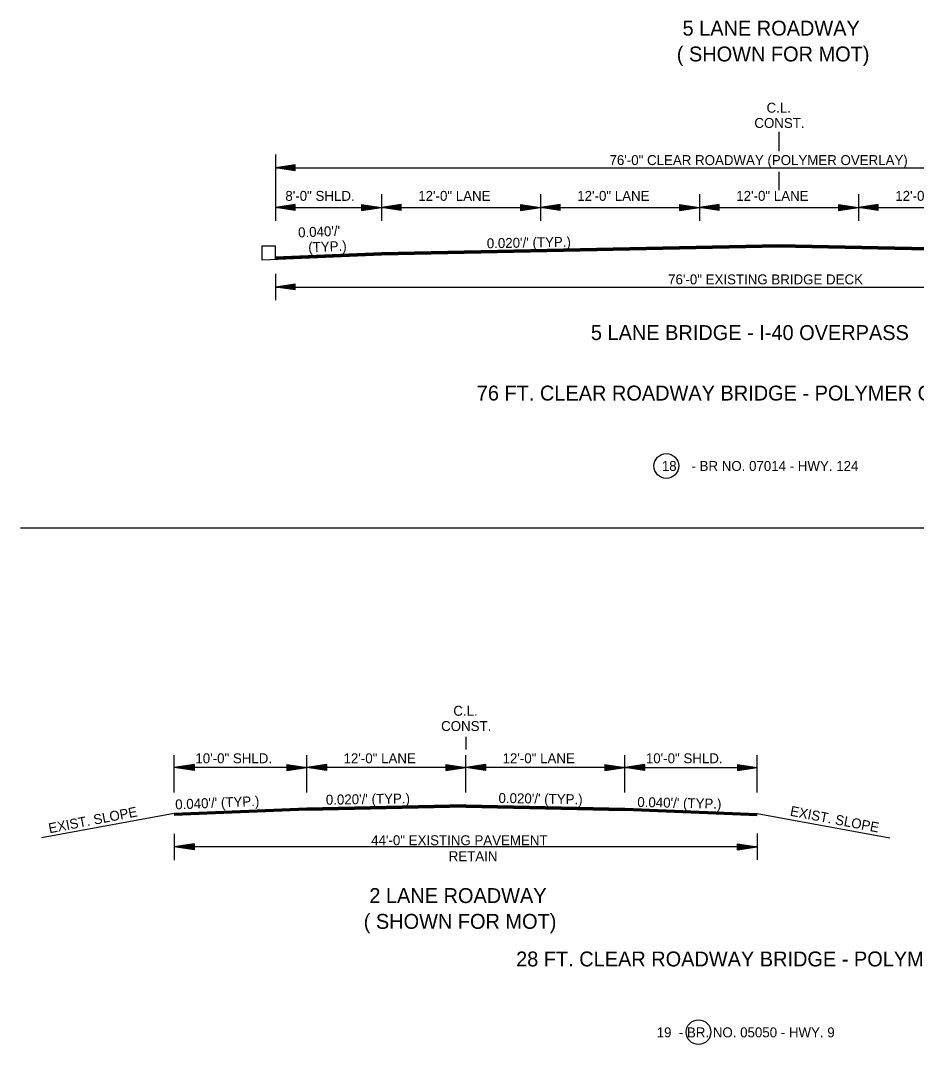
# Model space of a CAD drawing. Extents: x 550980 to 1930787, y -1972975 to 596640.
# Drawn here: x 551009 to 551685, y -1954146 to -1953373 of the extents above; entities that cross this region are included whole.
import ezdxf

# ---------------------------------------------------------------- set-up
doc = ezdxf.new("R2010")
doc.units = 0
doc.layers.add('R_Border', color=7, linetype='Continuous')
doc.layers.add('R_Draft', color=7, linetype='Continuous')

msp = doc.modelspace()

# ---------------------------------------------------------------- linework, layer by layer
at = {"layer": 'R_Border'}
for p, q in [((551581.34, -1953457.37), (551581.34, -1953471.87)), ((551201.34, -1953474.37), (551201.34, -1953524.37)), ((551216.34, -1953482.12), (551201.34, -1953484.37)), ((551201.34, -1953484.37), (551961.34, -1953484.37)), ((551216.34, -1953486.62), (551201.34, -1953484.37)), ((551216.34, -1953482.5), (551203.84, -1953484.37)), ((551216.34, -1953486.25), (551203.84, -1953484.37)), ((551216.34, -1953482.88), (551206.42, -1953484.37)), ((551216.34, -1953485.86), (551206.42, -1953484.37)), ((551216.34, -1953483.25), (551208.92, -1953484.37)), ((551216.34, -1953485.49), (551208.92, -1953484.37)), ((551216.34, -1953483.64), (551211.46, -1953484.37)), ((551216.34, -1953485.1), (551211.46, -1953484.37)), ((551216.34, -1953484.02), (551213.97, -1953484.37)), ((551216.34, -1953484.72), (551213.97, -1953484.37)), ((551216.34, -1953486.62), (551216.34, -1953482.12)), ((551581.34, -1953487.37), (551581.34, -1953501.37)), ((551281.34, -1953504.37), (551281.34, -1953524.37)), ((551401.34, -1953504.37), (551401.34, -1953524.37)), ((551521.34, -1953504.37), (551521.34, -1953524.37)), ((551641.34, -1953504.37), (551641.34, -1953524.37)), ((551216.34, -1953512.12), (551201.34, -1953514.37)), ((551201.34, -1953514.37), (551961.34, -1953514.37)), ((551216.34, -1953516.62), (551201.34, -1953514.37)), ((551216.34, -1953512.5), (551203.84, -1953514.37)), ((551216.34, -1953516.25), (551203.84, -1953514.37)), ((551216.34, -1953512.88), (551206.42, -1953514.37)), ((551216.34, -1953515.86), (551206.42, -1953514.37)), ((551216.34, -1953513.25), (551208.92, -1953514.37)), ((551216.34, -1953515.49), (551208.92, -1953514.37)), ((551216.34, -1953513.64), (551211.46, -1953514.37)), ((551216.34, -1953515.1), (551211.46, -1953514.37)), ((551216.34, -1953514.02), (551213.97, -1953514.37)), ((551216.34, -1953514.72), (551213.97, -1953514.37)), ((551216.34, -1953516.62), (551216.34, -1953512.12)), ((551266.34, -1953512.12), (551281.34, -1953514.37)), ((551266.34, -1953512.12), (551266.34, -1953516.62)), ((551266.34, -1953512.5), (551278.83, -1953514.37)), ((551266.34, -1953512.88), (551276.25, -1953514.37)), ((551266.34, -1953513.25), (551273.76, -1953514.37)), ((551266.34, -1953513.64), (551271.21, -1953514.37)), ((551266.34, -1953514.02), (551268.71, -1953514.37)), ((551266.34, -1953516.62), (551281.34, -1953514.37)), ((551266.34, -1953515.11), (551271.21, -1953514.37)), ((551266.34, -1953515.86), (551276.25, -1953514.37)), ((551266.34, -1953516.25), (551278.83, -1953514.37)), ((551266.34, -1953515.49), (551273.76, -1953514.37)), ((551266.34, -1953514.72), (551268.71, -1953514.37)), ((551296.34, -1953512.12), (551281.34, -1953514.37)), ((551296.34, -1953516.62), (551281.34, -1953514.37)), ((551296.34, -1953512.5), (551283.84, -1953514.37)), ((551296.34, -1953516.25), (551283.84, -1953514.37)), ((551296.34, -1953512.88), (551286.42, -1953514.37)), ((551296.34, -1953515.86), (551286.42, -1953514.37)), ((551296.34, -1953513.25), (551288.92, -1953514.37)), ((551296.34, -1953515.49), (551288.92, -1953514.37)), ((551296.34, -1953513.64), (551291.46, -1953514.37)), ((551296.34, -1953515.1), (551291.46, -1953514.37)), ((551296.34, -1953514.02), (551293.97, -1953514.37)), ((551296.34, -1953514.72), (551293.97, -1953514.37)), ((551296.34, -1953516.62), (551296.34, -1953512.12)), ((551386.34, -1953512.12), (551401.34, -1953514.37)), ((551386.34, -1953512.12), (551386.34, -1953516.62)), ((551386.34, -1953512.5), (551398.83, -1953514.37)), ((551386.34, -1953512.88), (551396.25, -1953514.37)), ((551386.34, -1953513.25), (551393.76, -1953514.37)), ((551386.34, -1953513.64), (551391.21, -1953514.37)), ((551386.34, -1953514.02), (551388.71, -1953514.37)), ((551386.34, -1953516.62), (551401.34, -1953514.37)), ((551386.34, -1953515.11), (551391.21, -1953514.37)), ((551386.34, -1953515.86), (551396.25, -1953514.37)), ((551386.34, -1953516.25), (551398.83, -1953514.37)), ((551386.34, -1953515.49), (551393.76, -1953514.37)), ((551386.34, -1953514.72), (551388.71, -1953514.37)), ((551416.34, -1953512.12), (551401.34, -1953514.37)), ((551416.34, -1953516.62), (551401.34, -1953514.37)), ((551416.34, -1953512.5), (551403.84, -1953514.37)), ((551416.34, -1953516.25), (551403.84, -1953514.37)), ((551416.34, -1953512.88), (551406.42, -1953514.37)), ((551416.34, -1953515.86), (551406.42, -1953514.37)), ((551416.34, -1953513.25), (551408.92, -1953514.37)), ((551416.34, -1953515.49), (551408.92, -1953514.37)), ((551416.34, -1953513.64), (551411.46, -1953514.37)), ((551416.34, -1953515.1), (551411.46, -1953514.37)), ((551416.34, -1953514.02), (551413.97, -1953514.37)), ((551416.34, -1953514.72), (551413.97, -1953514.37)), ((551416.34, -1953516.62), (551416.34, -1953512.12)), ((551506.34, -1953512.12), (551521.34, -1953514.37)), ((551506.34, -1953512.12), (551506.34, -1953516.62)), ((551506.34, -1953512.5), (551518.83, -1953514.37)), ((551506.34, -1953512.88), (551516.25, -1953514.37)), ((551506.34, -1953513.25), (551513.76, -1953514.37)), ((551506.34, -1953513.64), (551511.21, -1953514.37)), ((551506.34, -1953514.02), (551508.71, -1953514.37)), ((551506.34, -1953516.62), (551521.34, -1953514.37)), ((551506.34, -1953515.11), (551511.21, -1953514.37)), ((551506.34, -1953515.86), (551516.25, -1953514.37)), ((551506.34, -1953516.25), (551518.83, -1953514.37)), ((551506.34, -1953515.49), (551513.76, -1953514.37)), ((551506.34, -1953514.72), (551508.71, -1953514.37)), ((551536.34, -1953512.12), (551521.34, -1953514.37)), ((551536.34, -1953516.62), (551521.34, -1953514.37)), ((551536.34, -1953512.5), (551523.84, -1953514.37)), ((551536.34, -1953516.25), (551523.84, -1953514.37)), ((551536.34, -1953512.88), (551526.42, -1953514.37)), ((551536.34, -1953515.86), (551526.42, -1953514.37)), ((551536.34, -1953513.25), (551528.92, -1953514.37)), ((551536.34, -1953515.49), (551528.92, -1953514.37)), ((551536.34, -1953513.64), (551531.46, -1953514.37)), ((551536.34, -1953515.1), (551531.46, -1953514.37)), ((551536.34, -1953514.02), (551533.97, -1953514.37)), ((551536.34, -1953514.72), (551533.97, -1953514.37)), ((551536.34, -1953516.62), (551536.34, -1953512.12)), ((551626.34, -1953512.12), (551641.34, -1953514.37)), ((551626.34, -1953512.12), (551626.34, -1953516.62)), ((551626.34, -1953512.5), (551638.83, -1953514.37)), ((551626.34, -1953512.88), (551636.25, -1953514.37)), ((551626.34, -1953513.25), (551633.76, -1953514.37)), ((551626.34, -1953513.64), (551631.21, -1953514.37)), ((551626.34, -1953514.02), (551628.71, -1953514.37)), ((551626.34, -1953516.62), (551641.34, -1953514.37)), ((551626.34, -1953515.11), (551631.21, -1953514.37)), ((551626.34, -1953515.86), (551636.25, -1953514.37)), ((551626.34, -1953516.25), (551638.83, -1953514.37)), ((551626.34, -1953515.49), (551633.76, -1953514.37)), ((551626.34, -1953514.72), (551628.71, -1953514.37)), ((551656.34, -1953512.12), (551641.34, -1953514.37)), ((551656.34, -1953516.62), (551641.34, -1953514.37)), ((551656.34, -1953512.5), (551643.84, -1953514.37)), ((551656.34, -1953516.25), (551643.84, -1953514.37)), ((551656.34, -1953512.88), (551646.42, -1953514.37)), ((551656.34, -1953515.86), (551646.42, -1953514.37)), ((551656.34, -1953513.25), (551648.92, -1953514.37)), ((551656.34, -1953515.49), (551648.92, -1953514.37)), ((551656.34, -1953513.64), (551651.46, -1953514.37)), ((551656.34, -1953515.1), (551651.46, -1953514.37)), ((551656.34, -1953514.02), (551653.97, -1953514.37)), ((551656.34, -1953514.72), (551653.97, -1953514.37)), ((551656.34, -1953516.62), (551656.34, -1953512.12)), ((551201.34, -1953543.66), (551191.17, -1953543.66)), ((551191.17, -1953543.66), (551191.17, -1953553.78)), ((551201.34, -1953553.07), (551201.34, -1953543.66)), ((551201.34, -1953564.37), (551201.34, -1953584.37)), ((551216.34, -1953572.12), (551201.34, -1953574.37)), ((551201.34, -1953574.37), (551961.34, -1953574.37)), ((551216.34, -1953576.62), (551201.34, -1953574.37)), ((551216.34, -1953572.5), (551203.84, -1953574.37)), ((551216.34, -1953576.25), (551203.84, -1953574.37)), ((551216.34, -1953572.88), (551206.42, -1953574.37)), ((551216.34, -1953575.86), (551206.42, -1953574.37)), ((551216.34, -1953573.25), (551208.92, -1953574.37)), ((551216.34, -1953575.49), (551208.92, -1953574.37)), ((551216.34, -1953573.64), (551211.46, -1953574.37)), ((551216.34, -1953575.1), (551211.46, -1953574.37)), ((551216.34, -1953574.02), (551213.97, -1953574.37)), ((551216.34, -1953574.72), (551213.97, -1953574.37)), ((551216.34, -1953576.62), (551216.34, -1953572.12)), ((551008.97, -1953755.99), (552070.24, -1953755.99)), ((551344.96, -1953913.64), (551344.96, -1953923.19))]:
    msp.add_line(p, q, dxfattribs=at)
for points in [[(551191.17, -1953553.78), (551281.34, -1953550.17), (551581.34, -1953544.17), (551881.34, -1953550.17), (551971.51, -1953553.78)], [(551201.34, -1953551.57), (551281.34, -1953548.37), (551581.34, -1953542.37), (551881.34, -1953548.37), (551961.34, -1953551.57)], [(551201.34, -1953551.87), (551281.34, -1953548.67), (551581.34, -1953542.67), (551881.34, -1953548.67), (551961.34, -1953551.87)], [(551201.34, -1953552.17), (551281.34, -1953548.97), (551581.34, -1953542.97), (551881.34, -1953548.97), (551961.34, -1953552.17)], [(551201.34, -1953552.47), (551281.34, -1953549.27), (551581.34, -1953543.27), (551881.34, -1953549.27), (551961.34, -1953552.47)], [(551201.34, -1953552.77), (551281.34, -1953549.57), (551581.34, -1953543.57), (551881.34, -1953549.57), (551961.34, -1953552.77)], [(551201.34, -1953553.07), (551281.34, -1953549.87), (551581.34, -1953543.87), (551881.34, -1953549.87), (551961.34, -1953553.07)]]:
    msp.add_lwpolyline(points, dxfattribs=at)
for centre in [(551496.34, -1953709.37), (551520.64, -1954136.51)]:
    msp.add_circle(centre, 9.34, dxfattribs=at)
at = {"layer": 'R_Draft'}
for p, q in [((551124.96, -1953955.6), (551124.96, -1953927.64)), ((551139.96, -1953934.58), (551124.96, -1953936.83)), ((551139.96, -1953934.58), (551139.96, -1953939.08)), ((551209.96, -1953934.58), (551224.96, -1953936.83)), ((551209.96, -1953934.58), (551209.96, -1953939.08)), ((551224.96, -1953955.6), (551224.96, -1953927.64)), ((551239.96, -1953934.58), (551224.96, -1953936.83)), ((551239.96, -1953934.58), (551239.96, -1953939.08)), ((551329.96, -1953934.58), (551344.96, -1953936.83)), ((551329.96, -1953934.58), (551329.96, -1953939.08)), ((551344.96, -1953955.6), (551344.96, -1953927.64)), ((551359.96, -1953934.58), (551344.96, -1953936.83)), ((551359.96, -1953934.58), (551359.96, -1953939.08)), ((551449.96, -1953934.58), (551464.96, -1953936.83)), ((551449.96, -1953934.58), (551449.96, -1953939.08)), ((551464.96, -1953955.6), (551464.96, -1953927.64)), ((551479.96, -1953934.58), (551464.96, -1953936.83)), ((551479.96, -1953934.58), (551479.96, -1953939.08)), ((551549.96, -1953934.58), (551564.96, -1953936.83)), ((551549.96, -1953934.58), (551549.96, -1953939.08)), ((551564.96, -1953955.6), (551564.96, -1953927.64)), ((551224.96, -1953936.83), (551124.96, -1953936.83)), ((551139.96, -1953939.08), (551124.96, -1953936.83)), ((551139.96, -1953934.96), (551127.47, -1953936.83)), ((551139.96, -1953938.71), (551127.47, -1953936.83)), ((551139.96, -1953935.34), (551130.05, -1953936.83)), ((551139.96, -1953938.33), (551130.05, -1953936.83)), ((551139.96, -1953935.72), (551132.55, -1953936.83)), ((551139.96, -1953937.95), (551132.55, -1953936.83)), ((551139.96, -1953936.11), (551135.09, -1953936.83)), ((551139.96, -1953937.57), (551135.09, -1953936.83)), ((551139.96, -1953936.48), (551137.59, -1953936.83)), ((551139.96, -1953937.19), (551137.59, -1953936.83)), ((551209.96, -1953934.96), (551222.46, -1953936.83)), ((551209.96, -1953935.34), (551219.88, -1953936.83)), ((551209.96, -1953935.72), (551217.38, -1953936.83)), ((551209.96, -1953936.11), (551214.84, -1953936.83)), ((551209.96, -1953936.48), (551212.33, -1953936.83)), ((551209.96, -1953939.08), (551224.96, -1953936.83)), ((551209.96, -1953937.57), (551214.84, -1953936.83)), ((551209.96, -1953938.33), (551219.88, -1953936.83)), ((551209.96, -1953938.71), (551222.46, -1953936.83)), ((551209.96, -1953937.95), (551217.38, -1953936.83)), ((551209.96, -1953937.19), (551212.33, -1953936.83)), ((551344.96, -1953936.83), (551224.96, -1953936.83)), ((551239.96, -1953939.08), (551224.96, -1953936.83)), ((551239.96, -1953934.96), (551227.47, -1953936.83)), ((551239.96, -1953938.71), (551227.47, -1953936.83)), ((551239.96, -1953935.34), (551230.05, -1953936.83)), ((551239.96, -1953938.33), (551230.05, -1953936.83)), ((551239.96, -1953935.72), (551232.55, -1953936.83)), ((551239.96, -1953937.95), (551232.55, -1953936.83)), ((551239.96, -1953936.11), (551235.09, -1953936.83)), ((551239.96, -1953937.57), (551235.09, -1953936.83)), ((551239.96, -1953936.48), (551237.59, -1953936.83)), ((551239.96, -1953937.19), (551237.59, -1953936.83)), ((551329.96, -1953934.96), (551342.46, -1953936.83)), ((551329.96, -1953935.34), (551339.88, -1953936.83)), ((551329.96, -1953935.72), (551337.38, -1953936.83)), ((551329.96, -1953936.11), (551334.84, -1953936.83)), ((551329.96, -1953936.48), (551332.33, -1953936.83)), ((551329.96, -1953939.08), (551344.96, -1953936.83)), ((551329.96, -1953937.57), (551334.84, -1953936.83)), ((551329.96, -1953938.33), (551339.88, -1953936.83)), ((551329.96, -1953938.71), (551342.46, -1953936.83)), ((551329.96, -1953937.95), (551337.38, -1953936.83)), ((551329.96, -1953937.19), (551332.33, -1953936.83)), ((551464.96, -1953936.83), (551344.96, -1953936.83)), ((551359.96, -1953939.08), (551344.96, -1953936.83)), ((551359.96, -1953934.96), (551347.47, -1953936.83)), ((551359.96, -1953938.71), (551347.47, -1953936.83)), ((551359.96, -1953935.34), (551350.05, -1953936.83)), ((551359.96, -1953938.33), (551350.05, -1953936.83)), ((551359.96, -1953935.72), (551352.55, -1953936.83)), ((551359.96, -1953937.95), (551352.55, -1953936.83)), ((551359.96, -1953936.11), (551355.09, -1953936.83)), ((551359.96, -1953937.57), (551355.09, -1953936.83)), ((551359.96, -1953936.48), (551357.59, -1953936.83)), ((551359.96, -1953937.19), (551357.59, -1953936.83)), ((551449.96, -1953934.96), (551462.46, -1953936.83)), ((551449.96, -1953935.34), (551459.88, -1953936.83)), ((551449.96, -1953935.72), (551457.38, -1953936.83)), ((551449.96, -1953936.11), (551454.84, -1953936.83)), ((551449.96, -1953936.48), (551452.33, -1953936.83)), ((551449.96, -1953939.08), (551464.96, -1953936.83)), ((551449.96, -1953937.57), (551454.84, -1953936.83)), ((551449.96, -1953938.33), (551459.88, -1953936.83)), ((551449.96, -1953938.71), (551462.46, -1953936.83)), ((551449.96, -1953937.95), (551457.38, -1953936.83)), ((551449.96, -1953937.19), (551452.33, -1953936.83)), ((551464.96, -1953936.83), (551564.96, -1953936.83)), ((551479.96, -1953939.08), (551464.96, -1953936.83)), ((551479.96, -1953934.96), (551467.47, -1953936.83)), ((551479.96, -1953938.71), (551467.47, -1953936.83)), ((551479.96, -1953935.34), (551470.05, -1953936.83)), ((551479.96, -1953938.33), (551470.05, -1953936.83)), ((551479.96, -1953935.72), (551472.55, -1953936.83)), ((551479.96, -1953937.95), (551472.55, -1953936.83)), ((551479.96, -1953936.11), (551475.09, -1953936.83)), ((551479.96, -1953937.57), (551475.09, -1953936.83)), ((551479.96, -1953936.48), (551477.59, -1953936.83)), ((551479.96, -1953937.19), (551477.59, -1953936.83)), ((551549.96, -1953934.96), (551562.46, -1953936.83)), ((551549.96, -1953935.34), (551559.88, -1953936.83)), ((551549.96, -1953935.72), (551557.38, -1953936.83)), ((551549.96, -1953936.11), (551554.84, -1953936.83)), ((551549.96, -1953936.48), (551552.33, -1953936.83)), ((551549.96, -1953939.08), (551564.96, -1953936.83)), ((551549.96, -1953937.57), (551554.84, -1953936.83)), ((551549.96, -1953938.33), (551559.88, -1953936.83)), ((551549.96, -1953938.71), (551562.46, -1953936.83)), ((551549.96, -1953937.95), (551557.38, -1953936.83)), ((551549.96, -1953937.19), (551552.33, -1953936.83)), ((551344.96, -1953965.14), (551224.96, -1953967.54)), ((551344.96, -1953965.44), (551224.96, -1953967.84)), ((551344.96, -1953965.74), (551224.96, -1953968.14)), ((551344.96, -1953965.14), (551464.96, -1953967.54)), ((551344.96, -1953965.44), (551464.96, -1953967.84)), ((551344.96, -1953965.74), (551464.96, -1953968.14)), ((551124.96, -1953971.54), (551024.9, -1953989.92)), ((551224.96, -1953967.54), (551124.96, -1953971.54)), ((551224.96, -1953967.84), (551124.96, -1953971.84)), ((551224.96, -1953968.14), (551124.96, -1953972.14)), ((551224.96, -1953968.44), (551124.96, -1953972.44)), ((551224.96, -1953968.74), (551124.96, -1953972.74)), ((551224.96, -1953969.04), (551124.96, -1953973.04)), ((551344.96, -1953966.04), (551224.96, -1953968.44)), ((551344.96, -1953966.34), (551224.96, -1953968.74)), ((551344.96, -1953966.64), (551224.96, -1953969.04)), ((551344.96, -1953966.81), (551224.96, -1953969.21)), ((551344.96, -1953966.04), (551464.96, -1953968.44)), ((551344.96, -1953966.34), (551464.96, -1953968.74)), ((551344.96, -1953966.64), (551464.96, -1953969.04)), ((551344.96, -1953966.81), (551464.96, -1953969.21)), ((551464.96, -1953967.54), (551564.96, -1953971.54)), ((551464.96, -1953967.84), (551564.96, -1953971.84)), ((551464.96, -1953968.14), (551564.96, -1953972.14)), ((551464.96, -1953968.44), (551564.96, -1953972.44)), ((551464.96, -1953968.74), (551564.96, -1953972.74)), ((551464.96, -1953969.04), (551564.96, -1953973.04)), ((551564.96, -1953971.54), (551665.03, -1953989.92)), ((551124.96, -1953986.8), (551124.96, -1954006.8)), ((551564.96, -1953986.55), (551564.96, -1954006.55)), ((551139.96, -1953994.55), (551124.96, -1953996.8)), ((551139.96, -1953994.93), (551127.47, -1953996.8)), ((551139.96, -1953995.31), (551130.05, -1953996.8)), ((551139.96, -1953995.68), (551132.55, -1953996.8)), ((551139.96, -1953996.07), (551135.09, -1953996.8)), ((551139.96, -1953996.45), (551137.59, -1953996.8)), ((551139.96, -1953994.55), (551139.96, -1953999.05)), ((551549.96, -1953994.55), (551564.96, -1953996.8)), ((551549.96, -1953999.05), (551549.96, -1953994.55)), ((551549.96, -1953994.93), (551562.46, -1953996.8)), ((551549.96, -1953995.31), (551559.88, -1953996.8)), ((551549.96, -1953995.68), (551557.38, -1953996.8)), ((551549.96, -1953996.07), (551554.84, -1953996.8)), ((551549.96, -1953996.45), (551552.33, -1953996.8)), ((551139.96, -1953999.05), (551124.96, -1953996.8)), ((551564.96, -1953996.8), (551124.96, -1953996.8)), ((551139.96, -1953998.68), (551127.47, -1953996.8)), ((551139.96, -1953998.29), (551130.05, -1953996.8)), ((551139.96, -1953997.92), (551132.55, -1953996.8)), ((551139.96, -1953997.54), (551135.09, -1953996.8)), ((551139.96, -1953997.15), (551137.59, -1953996.8)), ((551549.96, -1953999.05), (551564.96, -1953996.8)), ((551549.96, -1953997.53), (551554.84, -1953996.8)), ((551549.96, -1953998.29), (551559.88, -1953996.8)), ((551549.96, -1953998.68), (551562.46, -1953996.8)), ((551549.96, -1953997.92), (551557.38, -1953996.8)), ((551549.96, -1953997.15), (551552.33, -1953996.8))]:
    msp.add_line(p, q, dxfattribs=at)

# ---------------------------------------------------------------- texts
at = {"layer": 'R_Border'}
for s, height, p in [('5 LANE ROADWAY', 11.25, (551508.61, -1953384.71)), ('( SHOWN FOR MOT)', 11.25, (551504.27, -1953404.19)), ('C.L.', 7.5, (551572.01, -1953442.87)), ('CONST.', 7.5, (551562.8, -1953454.37)), ('76\'-0" CLEAR ROADWAY (POLYMER OVERLAY)', 7.5, (551453.48, -1953482.37)), ('8\'-0" SHLD.', 7.5, (551208.86, -1953509.37)), ('12\'-0" LANE', 7.5, (551309.15, -1953509.37)), ('12\'-0" LANE', 7.5, (551429.15, -1953509.37)), ('12\'-0" LANE', 7.5, (551549.15, -1953509.37)), ('12\'-0" LANE', 7.5, (551669.15, -1953509.37)), ('76\'-0" EXISTING BRIDGE DECK', 7.5, (551497.72, -1953572.37)), ('5 LANE BRIDGE - I-40 OVERPASS', 11.25, (551439.43, -1953614.37)), ('76 FT. CLEAR ROADWAY BRIDGE - POLYMER OVERLAY', 11.25, (551353.33, -1953660)), ('18', 7.5, (551492.97, -1953713.12)), ('- BR NO. 07014 - HWY. 124', 7.5, (551515.34, -1953713.12)), ('C.L.', 7.5, (551335.63, -1953897.83)), ('CONST.', 7.5, (551326.42, -1953909.33)), ('( SHOWN FOR MOT)', 11.25, (551268, -1954058.56))]:
    msp.add_text(s, height=height, dxfattribs=at).set_placement(p)
for s, rotation, p in [("0.040'/' ", 2.2916, (551218.63, -1953536.97)), ('(TYP.)', 2.2916, (551226.29, -1953548.17)), ("0.020'/' (TYP.)", 1.1458, (551360.95, -1953545.18))]:
    msp.add_text(s, height=7.5, rotation=rotation, dxfattribs=at).set_placement(p)
at = {"layer": 'R_Draft'}
for s, height, p in [('10\'-0" SHLD.', 7.5, (551140.95, -1953933.66)), ('12\'-0" LANE', 7.5, (551252.78, -1953933.66)), ('12\'-0" LANE', 7.5, (551372.78, -1953933.66)), ('10\'-0" SHLD.', 7.5, (551480.95, -1953933.66)), ('44\'-0" EXISTING PAVEMENT ', 7.5, (551273.63, -1953995.48)), ('RETAIN', 7.5, (551332.16, -1954007.58)), ('2 LANE ROADWAY', 11.25, (551272.24, -1954039.1)), ('28 FT. CLEAR ROADWAY BRIDGE - POLYMER OVERLAY', 11.25, (551383, -1954086.93)), ('      19  - BR. NO. 05050 - HWY. 9', 7.5, (551472.37, -1954140.44))]:
    msp.add_text(s, height=height, dxfattribs=at).set_placement(p)
for s, rotation, p in [("  0.040'/' (TYP.)", 2.44797, (551120.34, -1953968.75)), ("0.020'/' (TYP.)", 0.97192, (551239.49, -1953964.94)), ("0.020'/' (TYP.)", 359.02808, (551369.67, -1953963.57)), ("0.040'/' (TYP.)", 358.68162, (551474.41, -1953966.58)), ('EXIST. SLOPE', 10.88286, (551030.88, -1953986.54)), ('EXIST. SLOPE', 349.11714, (551589.34, -1953973.14))]:
    msp.add_text(s, height=7.5, rotation=rotation, dxfattribs=at).set_placement(p)

doc.saveas('drawing.dxf')
